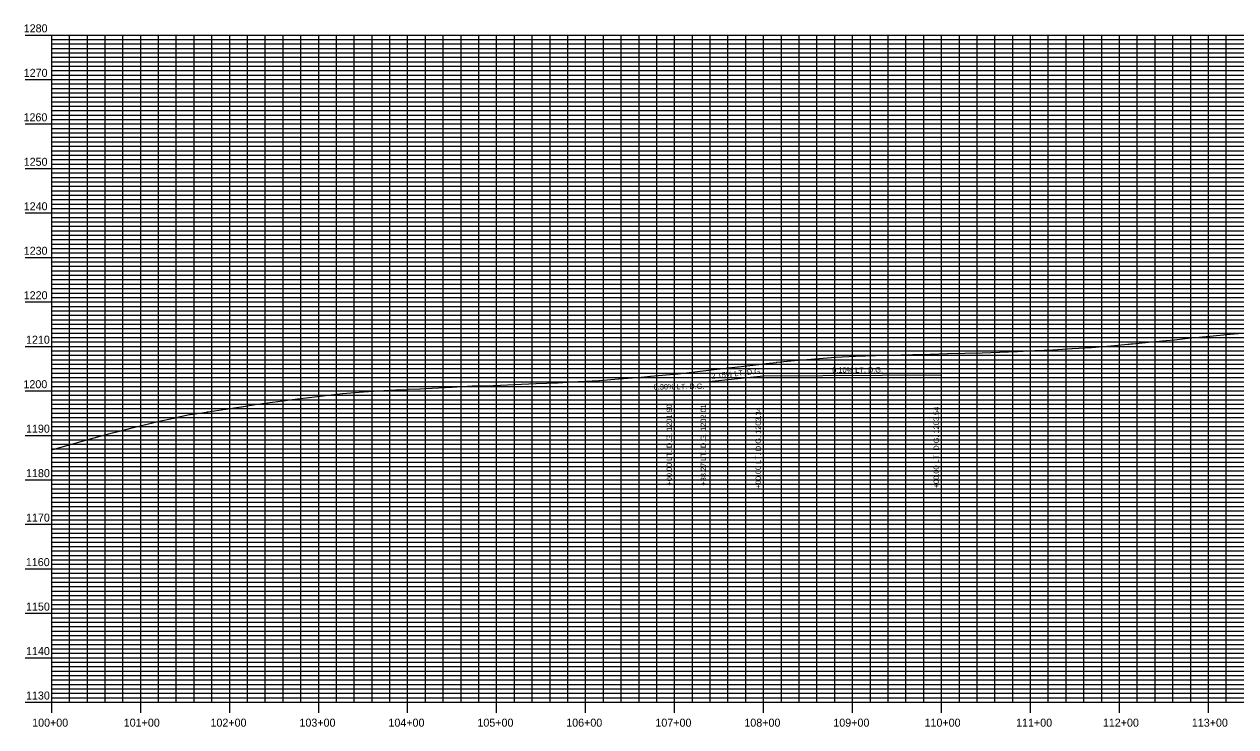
# Model space of a CAD drawing. Extents: x 604436 to 613248, y 742914 to 744515.
# Drawn here: x 605282 to 606644, y 743725 to 744515 of the extents above; entities that cross this region are included whole.
import ezdxf

# ---------------------------------------------------------------- set-up
doc = ezdxf.new("R2010")
doc.units = 0
for name, color, linetype in [('51', 7, 'Continuous'), ('Grid', 7, 'Continuous'), ('Grid_Labels', 7, 'Continuous'), ('Grid_Major', 7, 'Continuous'), ('Grid_Minor', 7, 'Continuous'), ('PRF_RD_Ex_PGL', 7, 'Continuous'), ('SHT_Annot_1', 7, 'Continuous'), ('Special_Ditch_LT', 7, 'Continuous')]:
    doc.layers.add(name, color=color, linetype=linetype)

msp = doc.modelspace()

# ---------------------------------------------------------------- linework, layer by layer
at = {"layer": 'Grid'}
for p, q in [((605283.1, 744502.8), (605313.1, 744502.8)), ((605283.1, 744502.8), (605313.1, 744502.8)), ((605313.1, 743752.8), (605313.1, 744502.8)), ((605313.1, 744497.8), (605316.1, 744497.8)), ((605313.1, 744492.8), (605316.1, 744492.8)), ((605313.1, 744487.8), (605316.1, 744487.8)), ((605313.1, 744482.8), (605316.1, 744482.8)), ((605313.1, 744477.8), (605316.1, 744477.8)), ((605313.1, 744472.8), (605316.1, 744472.8)), ((605313.1, 744467.8), (605316.1, 744467.8)), ((605313.1, 744462.8), (605316.1, 744462.8)), ((605283.1, 744452.8), (605313.1, 744452.8)), ((605313.1, 744457.8), (605316.1, 744457.8)), ((605313.1, 744447.8), (605316.1, 744447.8)), ((605313.1, 744442.8), (605316.1, 744442.8)), ((605313.1, 744437.8), (605316.1, 744437.8)), ((605313.1, 744432.8), (605316.1, 744432.8)), ((605313.1, 744427.8), (605316.1, 744427.8)), ((605313.1, 744422.8), (605316.1, 744422.8)), ((605313.1, 744417.8), (605316.1, 744417.8)), ((605313.1, 744412.8), (605316.1, 744412.8)), ((605313.1, 744407.8), (605316.1, 744407.8)), ((605283.1, 744402.8), (605313.1, 744402.8)), ((605313.1, 744397.8), (605316.1, 744397.8)), ((605313.1, 744392.8), (605316.1, 744392.8)), ((605313.1, 744387.8), (605316.1, 744387.8)), ((605313.1, 744382.8), (605316.1, 744382.8)), ((605313.1, 744377.8), (605316.1, 744377.8)), ((605313.1, 744372.8), (605316.1, 744372.8)), ((605313.1, 744367.8), (605316.1, 744367.8)), ((605283.1, 744352.8), (605313.1, 744352.8)), ((605313.1, 744362.8), (605316.1, 744362.8)), ((605313.1, 744357.8), (605316.1, 744357.8)), ((605313.1, 744347.8), (605316.1, 744347.8)), ((605313.1, 744342.8), (605316.1, 744342.8)), ((605313.1, 744337.8), (605316.1, 744337.8)), ((605313.1, 744332.8), (605316.1, 744332.8)), ((605313.1, 744327.8), (605316.1, 744327.8)), ((605313.1, 744322.8), (605316.1, 744322.8)), ((605313.1, 744317.8), (605316.1, 744317.8)), ((605313.1, 744312.8), (605316.1, 744312.8)), ((605283.1, 744302.8), (605313.1, 744302.8)), ((605313.1, 744307.8), (605316.1, 744307.8)), ((605313.1, 744297.8), (605316.1, 744297.8)), ((605313.1, 744292.8), (605316.1, 744292.8)), ((605313.1, 744287.8), (605316.1, 744287.8)), ((605313.1, 744282.8), (605316.1, 744282.8)), ((605313.1, 744277.8), (605316.1, 744277.8)), ((605313.1, 744272.8), (605316.1, 744272.8)), ((605313.1, 744267.8), (605316.1, 744267.8)), ((605313.1, 744262.8), (605316.1, 744262.8)), ((605313.1, 744257.8), (605316.1, 744257.8)), ((605283.1, 744252.8), (605313.1, 744252.8)), ((605313.1, 744247.8), (605316.1, 744247.8)), ((605313.1, 744242.8), (605316.1, 744242.8)), ((605313.1, 744237.8), (605316.1, 744237.8)), ((605313.1, 744232.8), (605316.1, 744232.8)), ((605313.1, 744227.8), (605316.1, 744227.8)), ((605313.1, 744222.8), (605316.1, 744222.8)), ((605313.1, 744217.8), (605316.1, 744217.8)), ((605283.1, 744202.8), (605313.1, 744202.8)), ((605313.1, 744212.8), (605316.1, 744212.8)), ((605313.1, 744207.8), (605316.1, 744207.8)), ((605313.1, 744197.8), (605316.1, 744197.8)), ((605313.1, 744192.8), (605316.1, 744192.8)), ((605313.1, 744187.8), (605316.1, 744187.8)), ((605313.1, 744182.8), (605316.1, 744182.8)), ((605313.1, 744177.8), (605316.1, 744177.8)), ((605313.1, 744172.8), (605316.1, 744172.8)), ((605313.1, 744167.8), (605316.1, 744167.8)), ((605313.1, 744162.8), (605316.1, 744162.8)), ((605283.1, 744152.8), (605313.1, 744152.8)), ((605313.1, 744157.8), (605316.1, 744157.8)), ((605313.1, 744147.8), (605316.1, 744147.8)), ((605313.1, 744142.8), (605316.1, 744142.8)), ((605313.1, 744137.8), (605316.1, 744137.8)), ((605313.1, 744132.8), (605316.1, 744132.8)), ((605313.1, 744127.8), (605316.1, 744127.8)), ((605313.1, 744122.8), (605316.1, 744122.8)), ((605313.1, 744117.8), (605316.1, 744117.8)), ((605313.1, 744112.8), (605316.1, 744112.8)), ((605313.1, 744107.8), (605316.1, 744107.8)), ((605283.1, 744102.8), (605313.1, 744102.8)), ((605313.1, 744097.8), (605316.1, 744097.8)), ((605313.1, 744092.8), (605316.1, 744092.8)), ((605313.1, 744087.8), (605316.1, 744087.8)), ((605313.1, 744082.8), (605316.1, 744082.8)), ((605313.1, 744077.8), (605316.1, 744077.8)), ((605313.1, 744072.8), (605316.1, 744072.8)), ((605313.1, 744067.8), (605316.1, 744067.8)), ((605283.1, 744052.8), (605313.1, 744052.8)), ((605313.1, 744062.8), (605316.1, 744062.8)), ((605313.1, 744057.8), (605316.1, 744057.8)), ((605313.1, 744047.8), (605316.1, 744047.8)), ((605313.1, 744042.8), (605316.1, 744042.8)), ((605313.1, 744037.8), (605316.1, 744037.8)), ((605313.1, 744032.8), (605316.1, 744032.8)), ((605313.1, 744027.8), (605316.1, 744027.8)), ((605313.1, 744022.8), (605316.1, 744022.8)), ((605313.1, 744017.8), (605316.1, 744017.8)), ((605313.1, 744012.8), (605316.1, 744012.8)), ((605283.1, 744002.8), (605313.1, 744002.8)), ((605313.1, 744007.8), (605316.1, 744007.8)), ((605313.1, 743997.8), (605316.1, 743997.8)), ((605313.1, 743992.8), (605316.1, 743992.8)), ((605313.1, 743987.8), (605316.1, 743987.8)), ((605313.1, 743982.8), (605316.1, 743982.8)), ((605313.1, 743977.8), (605316.1, 743977.8)), ((605313.1, 743972.8), (605316.1, 743972.8)), ((605313.1, 743967.8), (605316.1, 743967.8)), ((605313.1, 743962.8), (605316.1, 743962.8)), ((605313.1, 743957.8), (605316.1, 743957.8)), ((605283.1, 743952.8), (605313.1, 743952.8)), ((605313.1, 743947.8), (605316.1, 743947.8)), ((605313.1, 743942.8), (605316.1, 743942.8)), ((605313.1, 743937.8), (605316.1, 743937.8)), ((605313.1, 743932.8), (605316.1, 743932.8)), ((605313.1, 743927.8), (605316.1, 743927.8)), ((605313.1, 743922.8), (605316.1, 743922.8)), ((605313.1, 743917.8), (605316.1, 743917.8)), ((605283.1, 743902.8), (605313.1, 743902.8)), ((605313.1, 743912.8), (605316.1, 743912.8)), ((605313.1, 743907.8), (605316.1, 743907.8)), ((605313.1, 743897.8), (605316.1, 743897.8)), ((605313.1, 743892.8), (605316.1, 743892.8)), ((605313.1, 743887.8), (605316.1, 743887.8)), ((605313.1, 743882.8), (605316.1, 743882.8)), ((605313.1, 743877.8), (605316.1, 743877.8)), ((605313.1, 743872.8), (605316.1, 743872.8)), ((605313.1, 743867.8), (605316.1, 743867.8)), ((605313.1, 743862.8), (605316.1, 743862.8)), ((605283.1, 743852.8), (605313.1, 743852.8)), ((605313.1, 743857.8), (605316.1, 743857.8)), ((605313.1, 743847.8), (605316.1, 743847.8)), ((605313.1, 743842.8), (605316.1, 743842.8)), ((605313.1, 743837.8), (605316.1, 743837.8)), ((605313.1, 743832.8), (605316.1, 743832.8)), ((605313.1, 743827.8), (605316.1, 743827.8)), ((605313.1, 743822.8), (605316.1, 743822.8)), ((605313.1, 743817.8), (605316.1, 743817.8)), ((605313.1, 743812.8), (605316.1, 743812.8)), ((605313.1, 743807.8), (605316.1, 743807.8)), ((605283.1, 743802.8), (605313.1, 743802.8)), ((605313.1, 743797.8), (605316.1, 743797.8)), ((605313.1, 743792.8), (605316.1, 743792.8)), ((605313.1, 743787.8), (605316.1, 743787.8)), ((605313.1, 743782.8), (605316.1, 743782.8)), ((605313.1, 743777.8), (605316.1, 743777.8)), ((605313.1, 743772.8), (605316.1, 743772.8)), ((605313.1, 743767.8), (605316.1, 743767.8)), ((605283.1, 743752.8), (605313.1, 743752.8)), ((605313.1, 743762.8), (605316.1, 743762.8)), ((605313.1, 743757.8), (605316.1, 743757.8)), ((605313.1, 743752.8), (613213.1, 743752.8)), ((605313.1, 743740.8), (605313.1, 743752.8)), ((605413.1, 743740.8), (605413.1, 743752.8)), ((605513.1, 743740.8), (605513.1, 743752.8)), ((605613.1, 743740.8), (605613.1, 743752.8)), ((605713.1, 743740.8), (605713.1, 743752.8)), ((605813.1, 743740.8), (605813.1, 743752.8)), ((605913.1, 743740.8), (605913.1, 743752.8)), ((606013.1, 743740.8), (606013.1, 743752.8)), ((606113.1, 743740.8), (606113.1, 743752.8)), ((606213.1, 743740.8), (606213.1, 743752.8)), ((606313.1, 743740.8), (606313.1, 743752.8)), ((606413.1, 743740.8), (606413.1, 743752.8)), ((606513.1, 743740.8), (606513.1, 743752.8)), ((606613.1, 743740.8), (606613.1, 743752.8))]:
    msp.add_line(p, q, dxfattribs=at)
at = {"layer": 'Grid_Major'}
for p, q in [((605313.1, 744502.8), (613213.1, 744502.8)), ((605313.1, 744502.8), (613213.1, 744502.8)), ((605413.1, 743752.8), (605413.1, 744502.8)), ((605513.1, 743752.8), (605513.1, 744502.8)), ((605613.1, 743752.8), (605613.1, 744502.8)), ((605713.1, 743752.8), (605713.1, 744502.8)), ((605813.1, 743752.8), (605813.1, 744502.8)), ((605913.1, 743752.8), (605913.1, 744502.8)), ((606013.1, 743752.8), (606013.1, 744502.8)), ((606113.1, 743752.8), (606113.1, 744502.8)), ((606213.1, 743752.8), (606213.1, 744502.8)), ((606313.1, 743752.8), (606313.1, 744502.8)), ((606413.1, 743752.8), (606413.1, 744502.8)), ((606513.1, 743752.8), (606513.1, 744502.8)), ((606613.1, 743752.8), (606613.1, 744502.8)), ((605313.1, 744452.8), (613213.1, 744452.8)), ((605313.1, 744402.8), (613213.1, 744402.8)), ((605313.1, 744352.8), (613213.1, 744352.8)), ((605313.1, 744302.8), (613213.1, 744302.8)), ((605313.1, 744252.8), (613213.1, 744252.8)), ((605313.1, 744202.8), (613213.1, 744202.8)), ((605313.1, 744152.8), (613213.1, 744152.8)), ((605313.1, 744102.8), (613213.1, 744102.8)), ((605313.1, 744052.8), (613213.1, 744052.8)), ((605313.1, 744002.8), (613213.1, 744002.8)), ((605313.1, 743952.8), (613213.1, 743952.8)), ((605313.1, 743902.8), (613213.1, 743902.8)), ((605313.1, 743852.8), (613213.1, 743852.8)), ((605313.1, 743802.8), (613213.1, 743802.8))]:
    msp.add_line(p, q, dxfattribs=at)
at = {"layer": 'Grid_Minor'}
for p, q in [((605333.1, 743752.8), (605333.1, 744502.8)), ((605353.1, 743752.8), (605353.1, 744502.8)), ((605373.1, 743752.8), (605373.1, 744502.8)), ((605393.1, 743752.8), (605393.1, 744502.8)), ((605433.1, 743752.8), (605433.1, 744502.8)), ((605453.1, 743752.8), (605453.1, 744502.8)), ((605473.1, 743752.8), (605473.1, 744502.8)), ((605493.1, 743752.8), (605493.1, 744502.8)), ((605533.1, 743752.8), (605533.1, 744502.8)), ((605553.1, 743752.8), (605553.1, 744502.8)), ((605573.1, 743752.8), (605573.1, 744502.8)), ((605593.1, 743752.8), (605593.1, 744502.8)), ((605633.1, 743752.8), (605633.1, 744502.8)), ((605653.1, 743752.8), (605653.1, 744502.8)), ((605673.1, 743752.8), (605673.1, 744502.8)), ((605693.1, 743752.8), (605693.1, 744502.8)), ((605733.1, 743752.8), (605733.1, 744502.8)), ((605753.1, 743752.8), (605753.1, 744502.8)), ((605773.1, 743752.8), (605773.1, 744502.8)), ((605793.1, 743752.8), (605793.1, 744502.8)), ((605833.1, 743752.8), (605833.1, 744502.8)), ((605853.1, 743752.8), (605853.1, 744502.8)), ((605873.1, 743752.8), (605873.1, 744502.8)), ((605893.1, 743752.8), (605893.1, 744502.8)), ((605933.1, 743752.8), (605933.1, 744502.8)), ((605953.1, 743752.8), (605953.1, 744502.8)), ((605973.1, 743752.8), (605973.1, 744502.8)), ((605993.1, 743752.8), (605993.1, 744502.8)), ((606033.1, 743752.8), (606033.1, 744502.8)), ((606053.1, 743752.8), (606053.1, 744502.8)), ((606073.1, 743752.8), (606073.1, 744502.8)), ((606093.1, 743752.8), (606093.1, 744502.8)), ((606133.1, 743752.8), (606133.1, 744502.8)), ((606153.1, 743752.8), (606153.1, 744502.8)), ((606173.1, 743752.8), (606173.1, 744502.8)), ((606193.1, 743752.8), (606193.1, 744502.8)), ((606233.1, 743752.8), (606233.1, 744502.8)), ((606253.1, 743752.8), (606253.1, 744502.8)), ((606273.1, 743752.8), (606273.1, 744502.8)), ((606293.1, 743752.8), (606293.1, 744502.8)), ((606333.1, 743752.8), (606333.1, 744502.8)), ((606353.1, 743752.8), (606353.1, 744502.8)), ((606373.1, 743752.8), (606373.1, 744502.8)), ((606393.1, 743752.8), (606393.1, 744502.8)), ((606433.1, 743752.8), (606433.1, 744502.8)), ((606453.1, 743752.8), (606453.1, 744502.8)), ((606473.1, 743752.8), (606473.1, 744502.8)), ((606493.1, 743752.8), (606493.1, 744502.8)), ((606533.1, 743752.8), (606533.1, 744502.8)), ((606553.1, 743752.8), (606553.1, 744502.8)), ((606573.1, 743752.8), (606573.1, 744502.8)), ((606593.1, 743752.8), (606593.1, 744502.8)), ((606633.1, 743752.8), (606633.1, 744502.8)), ((605313.1, 744497.8), (613213.1, 744497.8)), ((605313.1, 744492.8), (613213.1, 744492.8)), ((605313.1, 744487.8), (613213.1, 744487.8)), ((605313.1, 744482.8), (613213.1, 744482.8)), ((605313.1, 744477.8), (613213.1, 744477.8)), ((605313.1, 744472.8), (613213.1, 744472.8)), ((605313.1, 744467.8), (613213.1, 744467.8)), ((605313.1, 744462.8), (613213.1, 744462.8)), ((605313.1, 744457.8), (613213.1, 744457.8)), ((605313.1, 744447.8), (613213.1, 744447.8)), ((605313.1, 744442.8), (613213.1, 744442.8)), ((605313.1, 744437.8), (613213.1, 744437.8)), ((605313.1, 744432.8), (613213.1, 744432.8)), ((605313.1, 744427.8), (613213.1, 744427.8)), ((605313.1, 744422.8), (613213.1, 744422.8)), ((605313.1, 744417.8), (613213.1, 744417.8)), ((605313.1, 744412.8), (613213.1, 744412.8)), ((605313.1, 744407.8), (613213.1, 744407.8)), ((605313.1, 744397.8), (613213.1, 744397.8)), ((605313.1, 744392.8), (613213.1, 744392.8)), ((605313.1, 744387.8), (613213.1, 744387.8)), ((605313.1, 744382.8), (613213.1, 744382.8)), ((605313.1, 744377.8), (613213.1, 744377.8)), ((605313.1, 744372.8), (613213.1, 744372.8)), ((605313.1, 744367.8), (613213.1, 744367.8)), ((605313.1, 744362.8), (613213.1, 744362.8)), ((605313.1, 744357.8), (613213.1, 744357.8)), ((605313.1, 744347.8), (613213.1, 744347.8)), ((605313.1, 744342.8), (613213.1, 744342.8)), ((605313.1, 744337.8), (613213.1, 744337.8)), ((605313.1, 744332.8), (613213.1, 744332.8)), ((605313.1, 744327.8), (613213.1, 744327.8)), ((605313.1, 744322.8), (613213.1, 744322.8)), ((605313.1, 744317.8), (613213.1, 744317.8)), ((605313.1, 744312.8), (613213.1, 744312.8)), ((605313.1, 744307.8), (613213.1, 744307.8)), ((605313.1, 744297.8), (613213.1, 744297.8)), ((605313.1, 744292.8), (613213.1, 744292.8)), ((605313.1, 744287.8), (613213.1, 744287.8)), ((605313.1, 744282.8), (613213.1, 744282.8)), ((605313.1, 744277.8), (613213.1, 744277.8)), ((605313.1, 744272.8), (613213.1, 744272.8)), ((605313.1, 744267.8), (613213.1, 744267.8)), ((605313.1, 744262.8), (613213.1, 744262.8)), ((605313.1, 744257.8), (613213.1, 744257.8)), ((605313.1, 744247.8), (613213.1, 744247.8)), ((605313.1, 744242.8), (613213.1, 744242.8)), ((605313.1, 744237.8), (613213.1, 744237.8)), ((605313.1, 744232.8), (613213.1, 744232.8)), ((605313.1, 744227.8), (613213.1, 744227.8)), ((605313.1, 744222.8), (613213.1, 744222.8)), ((605313.1, 744217.8), (613213.1, 744217.8)), ((605313.1, 744212.8), (613213.1, 744212.8)), ((605313.1, 744207.8), (613213.1, 744207.8)), ((605313.1, 744197.8), (613213.1, 744197.8)), ((605313.1, 744192.8), (613213.1, 744192.8)), ((605313.1, 744187.8), (613213.1, 744187.8)), ((605313.1, 744182.8), (613213.1, 744182.8)), ((605313.1, 744177.8), (613213.1, 744177.8)), ((605313.1, 744172.8), (613213.1, 744172.8)), ((605313.1, 744167.8), (613213.1, 744167.8)), ((605313.1, 744162.8), (613213.1, 744162.8)), ((605313.1, 744157.8), (613213.1, 744157.8)), ((605313.1, 744147.8), (613213.1, 744147.8)), ((605313.1, 744142.8), (613213.1, 744142.8)), ((605313.1, 744137.8), (613213.1, 744137.8)), ((605313.1, 744132.8), (613213.1, 744132.8)), ((605313.1, 744127.8), (613213.1, 744127.8)), ((605313.1, 744122.8), (613213.1, 744122.8)), ((605313.1, 744117.8), (613213.1, 744117.8)), ((605313.1, 744112.8), (613213.1, 744112.8)), ((605313.1, 744107.8), (613213.1, 744107.8)), ((605313.1, 744097.8), (613213.1, 744097.8)), ((605313.1, 744092.8), (613213.1, 744092.8)), ((605313.1, 744087.8), (613213.1, 744087.8)), ((605313.1, 744082.8), (613213.1, 744082.8)), ((605313.1, 744077.8), (613213.1, 744077.8)), ((605313.1, 744072.8), (613213.1, 744072.8)), ((605313.1, 744067.8), (613213.1, 744067.8)), ((605313.1, 744062.8), (613213.1, 744062.8)), ((605313.1, 744057.8), (613213.1, 744057.8)), ((605313.1, 744047.8), (613213.1, 744047.8)), ((605313.1, 744042.8), (613213.1, 744042.8)), ((605313.1, 744037.8), (613213.1, 744037.8)), ((605313.1, 744032.8), (613213.1, 744032.8)), ((605313.1, 744027.8), (613213.1, 744027.8)), ((605313.1, 744022.8), (613213.1, 744022.8)), ((605313.1, 744017.8), (613213.1, 744017.8)), ((605313.1, 744012.8), (613213.1, 744012.8)), ((605313.1, 744007.8), (613213.1, 744007.8)), ((605313.1, 743997.8), (613213.1, 743997.8)), ((605313.1, 743992.8), (613213.1, 743992.8)), ((605313.1, 743987.8), (613213.1, 743987.8)), ((605313.1, 743982.8), (613213.1, 743982.8)), ((605313.1, 743977.8), (613213.1, 743977.8)), ((605313.1, 743972.8), (613213.1, 743972.8)), ((605313.1, 743967.8), (613213.1, 743967.8)), ((605313.1, 743962.8), (613213.1, 743962.8)), ((605313.1, 743957.8), (613213.1, 743957.8)), ((605313.1, 743947.8), (613213.1, 743947.8)), ((605313.1, 743942.8), (613213.1, 743942.8)), ((605313.1, 743937.8), (613213.1, 743937.8)), ((605313.1, 743932.8), (613213.1, 743932.8)), ((605313.1, 743927.8), (613213.1, 743927.8)), ((605313.1, 743922.8), (613213.1, 743922.8)), ((605313.1, 743917.8), (613213.1, 743917.8)), ((605313.1, 743912.8), (613213.1, 743912.8)), ((605313.1, 743907.8), (613213.1, 743907.8)), ((605313.1, 743897.8), (613213.1, 743897.8)), ((605313.1, 743892.8), (613213.1, 743892.8)), ((605313.1, 743887.8), (613213.1, 743887.8)), ((605313.1, 743882.8), (613213.1, 743882.8)), ((605313.1, 743877.8), (613213.1, 743877.8)), ((605313.1, 743872.8), (613213.1, 743872.8)), ((605313.1, 743867.8), (613213.1, 743867.8)), ((605313.1, 743862.8), (613213.1, 743862.8)), ((605313.1, 743857.8), (613213.1, 743857.8)), ((605313.1, 743847.8), (613213.1, 743847.8)), ((605313.1, 743842.8), (613213.1, 743842.8)), ((605313.1, 743837.8), (613213.1, 743837.8)), ((605313.1, 743832.8), (613213.1, 743832.8)), ((605313.1, 743827.8), (613213.1, 743827.8)), ((605313.1, 743822.8), (613213.1, 743822.8)), ((605313.1, 743817.8), (613213.1, 743817.8)), ((605313.1, 743812.8), (613213.1, 743812.8)), ((605313.1, 743807.8), (613213.1, 743807.8)), ((605313.1, 743797.8), (613213.1, 743797.8)), ((605313.1, 743792.8), (613213.1, 743792.8)), ((605313.1, 743787.8), (613213.1, 743787.8)), ((605313.1, 743782.8), (613213.1, 743782.8)), ((605313.1, 743777.8), (613213.1, 743777.8)), ((605313.1, 743772.8), (613213.1, 743772.8)), ((605313.1, 743767.8), (613213.1, 743767.8)), ((605313.1, 743762.8), (613213.1, 743762.8)), ((605313.1, 743757.8), (613213.1, 743757.8))]:
    msp.add_line(p, q, dxfattribs=at)
at = {"layer": 'PRF_RD_Ex_PGL'}
msp.add_lwpolyline([(605313.1, 744036.4), (605315.7, 744037.2), (605330.1, 744041.5), (605330.1, 744041.5), (605348.8, 744046.7), (605348.9, 744046.7), (605350, 744047), (605367.5, 744052), (605381.4, 744055.6), (605384.2, 744056.3), (605386.2, 744056.8), (605386.3, 744056.8), (605404.9, 744061.6), (605405, 744061.6), (605418.4, 744064.8), (605418.5, 744064.9), (605418.7, 744064.9), (605432.2, 744068.2), (605432.5, 744068.2), (605450.1, 744072.1), (605450.5, 744072.2), (605452.6, 744072.7), (605468, 744076.1), (605468.5, 744076.2), (605486.9, 744079), (605488.1, 744079.2), (605488.5, 744079.3), (605508.2, 744082.3), (605508.6, 744082.3), (605521.1, 744084.2), (605526.1, 744085), (605526.5, 744085), (605544, 744087.7), (605544.5, 744087.7), (605566.7, 744090.8), (605567.2, 744090.8), (605589.4, 744093.9), (605589.7, 744093.9), (605602, 744095.4), (605602.3, 744095.4), (605614.6, 744097), (605614.8, 744097), (605627.3, 744098.5), (605627.4, 744098.5), (605639.9, 744100), (605640.1, 744100), (605663.1, 744101.6), (605663.4, 744101.6), (605686.3, 744103.2), (605686.5, 744103.2), (605699.8, 744103.9), (605700, 744103.9), (605713.2, 744104.5), (605713.5, 744104.6), (605726.7, 744105.2), (605727, 744105.2), (605740.2, 744105.9), (605740.6, 744105.9), (605762.9, 744107.1), (605763.3, 744107.1), (605785.6, 744108.3), (605786.1, 744108.4), (605809.3, 744109), (605809.7, 744109), (605833.1, 744109.8), (605833.1, 744109.8), (605857.2, 744110.9), (605857.3, 744110.9), (605857.4, 744110.9), (605881.4, 744111.9), (605881.5, 744111.9), (605881.7, 744111.9), (605904.9, 744113.2), (605905.2, 744113.2), (605928.3, 744114.4), (605928.7, 744114.4), (605950.2, 744116.2), (605950.3, 744116.2), (605965.7, 744117.5), (605972, 744118), (605972.1, 744118), (605986, 744119.2), (605994.5, 744119.9), (605994.6, 744120), (606017, 744121.9), (606017, 744121.9), (606038.8, 744124.4), (606038.9, 744124.5), (606060.6, 744127), (606060.8, 744127), (606060.9, 744127), (606084.1, 744129.8), (606084.4, 744129.8), (606107.5, 744132.6), (606107.8, 744132.6), (606108.2, 744132.7), (606127.8, 744134.8), (606128.1, 744134.9), (606147.8, 744137), (606147.9, 744137), (606170.8, 744138.8), (606171, 744138.8), (606193.8, 744140.6), (606194, 744140.6), (606216.3, 744141.7), (606216.4, 744141.7), (606238.7, 744142.7), (606238.8, 744142.7), (606259.7, 744143.1), (606259.7, 744143.1), (606267.7, 744143.3), (606280.7, 744143.6), (606280.8, 744143.6), (606280.8, 744143.6), (606286.2, 744143.8), (606300.1, 744144.2), (606300.2, 744144.2), (606319.5, 744144.9), (606319.7, 744144.9), (606339.1, 744145.3), (606339.3, 744145.3), (606358.7, 744145.7), (606358.8, 744145.7), (606378.4, 744146.4), (606378.7, 744146.4), (606398.2, 744147.1), (606398.5, 744147.1), (606418.1, 744148), (606418.5, 744148.1), (606438, 744149), (606438.6, 744149), (606459.5, 744150.3), (606460.1, 744150.4), (606481.1, 744151.6), (606481.5, 744151.7), (606503.4, 744153.6), (606503.6, 744153.6), (606522.3, 744155.2), (606524.4, 744155.4), (606525.7, 744155.5), (606525.7, 744155.5), (606528.2, 744155.7), (606545.6, 744157.4), (606545.7, 744157.4), (606565.5, 744159.3), (606565.6, 744159.3), (606575, 744160.3), (606590, 744161.9), (606590.1, 744161.9), (606614.5, 744164.4), (606614.5, 744164.4), (606637.4, 744166.4), (606637.6, 744166.4), (606660.5, 744168.4)], dxfattribs=at)
at = {"layer": 'Special_Ditch_LT'}
msp.add_line((606313.1, 744120.6), (606113.1, 744119.5), dxfattribs=at)
msp.add_lwpolyline([(606113.1, 744119.5), (606051.4, 744112.9), (606013.1, 744112.3)], dxfattribs=at)

# ---------------------------------------------------------------- texts
at = {"layer": '51'}
msp.add_text('-', height=0.0001, dxfattribs=at).set_placement((605313.1, 743752.8))
at = {"layer": 'Grid_Labels'}
for s, p in [('1280', (605281.6, 744505.8)), ('1280', (605281.6, 744505.8)), ('1270', (605281.6, 744455.8)), ('1260', (605281.4, 744405.8)), ('1250', (605281.6, 744355.8)), ('1240', (605281.6, 744305.8)), ('1230', (605281.6, 744255.8)), ('1220', (605281.6, 744205.8)), ('1210', (605284.2, 744155.8)), ('1200', (605281.3, 744105.8)), ('1190', (605284.2, 744055.8)), ('1180', (605284.2, 744005.8)), ('1170', (605284.2, 743955.8)), ('1160', (605284, 743905.8)), ('1150', (605284.2, 743855.8)), ('1140', (605284.2, 743805.8)), ('1130', (605284.2, 743755.8)), ('100+00', (605291.1, 743725.3)), ('101+00', (605394, 743725.3)), ('102+00', (605491.5, 743725.3)), ('103+00', (605591.5, 743725.3)), ('104+00', (605691.5, 743725.3)), ('105+00', (605791.5, 743725.3)), ('106+00', (605891.3, 743725.3)), ('107+00', (605991.5, 743725.3)), ('108+00', (606091.5, 743725.3)), ('109+00', (606191.5, 743725.3)), ('110+00', (606294, 743725.3)), ('111+00', (606396.9, 743725.3)), ('112+00', (606494.4, 743725.3)), ('113+00', (606594.4, 743725.3))]:
    msp.add_text(s, height=9, dxfattribs=at).set_placement(p)
at = {"layer": 'SHT_Annot_1'}
for s, rotation, p in [('2.15% LT. D.G.', 6.1486, (606054.9, 744116.3)), ('0.10% LT. D.G.', 0.3151, (606190.3, 744123.2)), ('0.30% LT. D.G.', 0.8234, (605989.6, 744104.2)), ('+00.00 LT. D.G. 1201.90', 90, (606010.1, 743996.3)), ('+38.27 LT. D.G. 1202.01', 90, (606048.4, 743996.3)), ('+00.00 LT. D.G. 1203.34', 90, (606110.1, 743992.9)), ('+00.00 LT. D.G. 1203.54', 90, (606310.1, 743993.4))]:
    msp.add_text(s, height=6, rotation=rotation, dxfattribs=at).set_placement(p)

doc.saveas('drawing.dxf')
